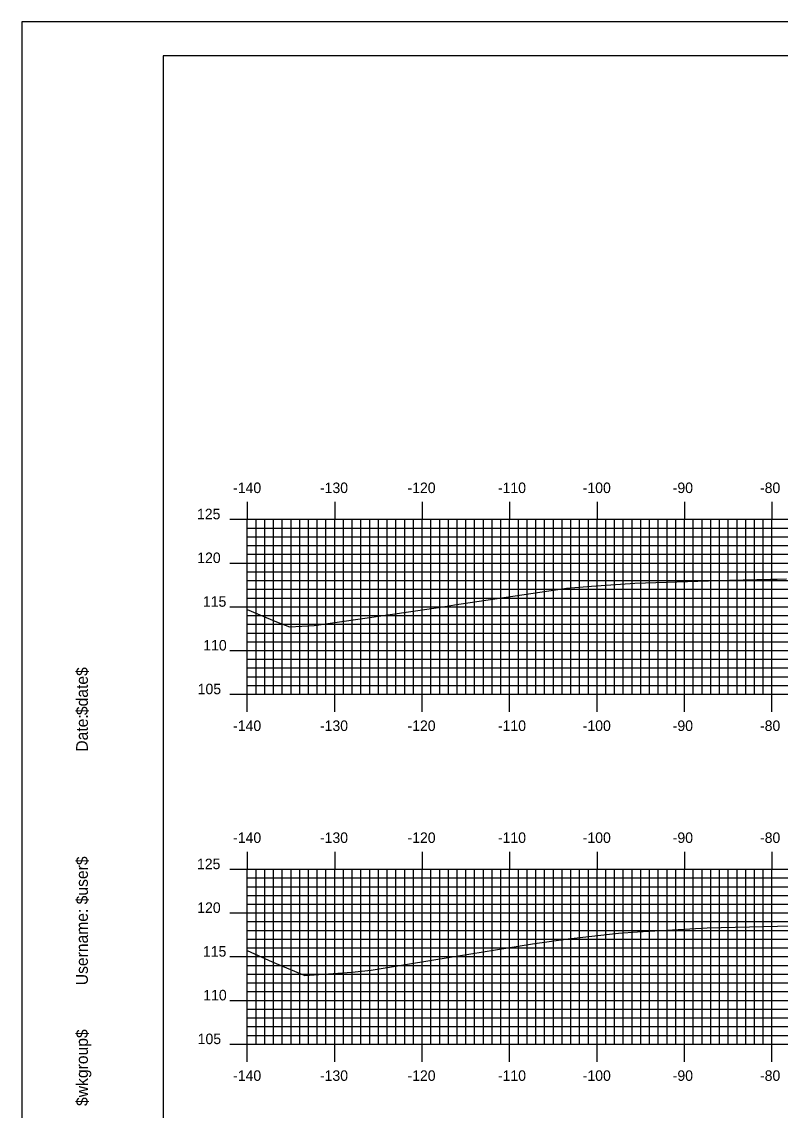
# Model space of a CAD drawing. Extents: x 855074 to 855418, y 366605 to 366825.
# Drawn here: x 855074.3 to 855161, y 366700.5 to 366824.9 of the extents above; entities that cross this region are included whole.
import ezdxf

# ---------------------------------------------------------------- set-up
doc = ezdxf.new("R2010")
doc.units = 0
for name, color, linetype in [('BORDER', 7, 'Continuous'), ('H_V ANNOTATION', 7, 'Continuous'), ('MAJOR', 7, 'Continuous'), ('MINOR', 7, 'Continuous'), ('PLOT BOUNDARY', 7, 'Continuous'), ('S_Roadway_Centerline', 7, 'Continuous')]:
    doc.layers.add(name, color=color, linetype=linetype)

msp = doc.modelspace()

# ---------------------------------------------------------------- linework, layer by layer
at = {"layer": 'BORDER'}
msp.add_lwpolyline([(855090.47, 366611.06), (855410.47, 366611.06), (855410.47, 366821.06), (855090.47, 366821.06)], close=True, dxfattribs=at)
at = {"layer": 'MAJOR'}
for p, q in [((855100.07, 366770.06), (855100.07, 366768.06)), ((855110.07, 366770.06), (855110.07, 366768.06)), ((855120.07, 366770.06), (855120.07, 366768.06)), ((855130.07, 366770.06), (855130.07, 366768.06)), ((855140.07, 366770.06), (855140.07, 366768.06)), ((855150.07, 366770.06), (855150.07, 366768.06)), ((855160.07, 366770.06), (855160.07, 366768.06)), ((855098.07, 366768.06), (855100.07, 366768.06)), ((855100.07, 366768.06), (855380.07, 366768.06)), ((855100.07, 366748.06), (855100.07, 366768.06)), ((855100.07, 366748.06), (855100.07, 366768.06)), ((855100.07, 366768.06), (855380.07, 366768.06)), ((855110.07, 366748.06), (855110.07, 366768.06)), ((855120.07, 366748.06), (855120.07, 366768.06)), ((855130.07, 366748.06), (855130.07, 366768.06)), ((855140.07, 366748.06), (855140.07, 366768.06)), ((855150.07, 366748.06), (855150.07, 366768.06)), ((855160.07, 366748.06), (855160.07, 366768.06)), ((855098.07, 366763.06), (855100.07, 366763.06)), ((855100.07, 366763.06), (855380.07, 366763.06)), ((855098.07, 366758.06), (855100.07, 366758.06)), ((855100.07, 366758.06), (855380.07, 366758.06)), ((855098.07, 366753.06), (855100.07, 366753.06)), ((855100.07, 366753.06), (855380.07, 366753.06)), ((855098.07, 366748.06), (855100.07, 366748.06)), ((855100.07, 366748.06), (855380.07, 366748.06)), ((855100.07, 366748.06), (855380.07, 366748.06)), ((855100.07, 366746.05), (855100.07, 366748.06)), ((855110.07, 366746.05), (855110.07, 366748.06)), ((855120.07, 366746.05), (855120.07, 366748.06)), ((855130.07, 366746.05), (855130.07, 366748.06)), ((855140.07, 366746.05), (855140.07, 366748.06)), ((855150.07, 366746.05), (855150.07, 366748.06)), ((855160.07, 366746.05), (855160.07, 366748.06)), ((855100.07, 366730.06), (855100.07, 366728.06)), ((855110.07, 366730.06), (855110.07, 366728.06)), ((855120.07, 366730.06), (855120.07, 366728.06)), ((855130.07, 366730.06), (855130.07, 366728.06)), ((855140.07, 366730.06), (855140.07, 366728.06)), ((855150.07, 366730.06), (855150.07, 366728.06)), ((855160.07, 366730.06), (855160.07, 366728.06)), ((855098.07, 366728.06), (855100.07, 366728.06)), ((855100.07, 366728.06), (855380.07, 366728.06)), ((855100.07, 366708.06), (855100.07, 366728.06)), ((855100.07, 366708.06), (855100.07, 366728.06)), ((855100.07, 366728.06), (855380.07, 366728.06)), ((855110.07, 366708.06), (855110.07, 366728.06)), ((855120.07, 366708.06), (855120.07, 366728.06)), ((855130.07, 366708.06), (855130.07, 366728.06)), ((855140.07, 366708.06), (855140.07, 366728.06)), ((855150.07, 366708.06), (855150.07, 366728.06)), ((855160.07, 366708.06), (855160.07, 366728.06)), ((855098.07, 366723.06), (855100.07, 366723.06)), ((855100.07, 366723.06), (855380.07, 366723.06)), ((855098.07, 366718.06), (855100.07, 366718.06)), ((855100.07, 366718.06), (855380.07, 366718.06)), ((855098.07, 366713.06), (855100.07, 366713.06)), ((855100.07, 366713.06), (855380.07, 366713.06)), ((855098.07, 366708.06), (855100.07, 366708.06)), ((855100.07, 366708.06), (855380.07, 366708.06)), ((855100.07, 366708.06), (855380.07, 366708.06)), ((855100.07, 366706.05), (855100.07, 366708.06)), ((855110.07, 366706.05), (855110.07, 366708.06)), ((855120.07, 366706.05), (855120.07, 366708.06)), ((855130.07, 366706.05), (855130.07, 366708.06)), ((855140.07, 366706.05), (855140.07, 366708.06)), ((855150.07, 366706.05), (855150.07, 366708.06)), ((855160.07, 366706.05), (855160.07, 366708.06))]:
    msp.add_line(p, q, dxfattribs=at)
at = {"layer": 'MINOR'}
for p, q in [((855101.07, 366748.06), (855101.07, 366768.06)), ((855102.07, 366748.06), (855102.07, 366768.06)), ((855103.07, 366748.06), (855103.07, 366768.06)), ((855104.07, 366748.06), (855104.07, 366768.06)), ((855105.07, 366748.06), (855105.07, 366768.06)), ((855106.07, 366748.06), (855106.07, 366768.06)), ((855107.07, 366748.06), (855107.07, 366768.06)), ((855108.07, 366748.06), (855108.07, 366768.06)), ((855109.07, 366748.06), (855109.07, 366768.06)), ((855111.07, 366748.06), (855111.07, 366768.06)), ((855112.07, 366748.06), (855112.07, 366768.06)), ((855113.07, 366748.06), (855113.07, 366768.06)), ((855114.07, 366748.06), (855114.07, 366768.06)), ((855115.07, 366748.06), (855115.07, 366768.06)), ((855116.07, 366748.06), (855116.07, 366768.06)), ((855117.07, 366748.06), (855117.07, 366768.06)), ((855118.07, 366748.06), (855118.07, 366768.06)), ((855119.07, 366748.06), (855119.07, 366768.06)), ((855121.07, 366748.06), (855121.07, 366768.06)), ((855122.07, 366748.06), (855122.07, 366768.06)), ((855123.07, 366748.06), (855123.07, 366768.06)), ((855124.07, 366748.06), (855124.07, 366768.06)), ((855125.07, 366748.06), (855125.07, 366768.06)), ((855126.07, 366748.06), (855126.07, 366768.06)), ((855127.07, 366748.06), (855127.07, 366768.06)), ((855128.07, 366748.06), (855128.07, 366768.06)), ((855129.07, 366748.06), (855129.07, 366768.06)), ((855131.07, 366748.06), (855131.07, 366768.06)), ((855132.07, 366748.06), (855132.07, 366768.06)), ((855133.07, 366748.06), (855133.07, 366768.06)), ((855134.07, 366748.06), (855134.07, 366768.06)), ((855135.07, 366748.06), (855135.07, 366768.06)), ((855136.07, 366748.06), (855136.07, 366768.06)), ((855137.07, 366748.06), (855137.07, 366768.06)), ((855138.07, 366748.06), (855138.07, 366768.06)), ((855139.07, 366748.06), (855139.07, 366768.06)), ((855141.07, 366748.06), (855141.07, 366768.06)), ((855142.07, 366748.06), (855142.07, 366768.06)), ((855143.07, 366748.06), (855143.07, 366768.06)), ((855144.07, 366748.06), (855144.07, 366768.06)), ((855145.07, 366748.06), (855145.07, 366768.06)), ((855146.07, 366748.06), (855146.07, 366768.06)), ((855147.07, 366748.06), (855147.07, 366768.06)), ((855148.07, 366748.06), (855148.07, 366768.06)), ((855149.07, 366748.06), (855149.07, 366768.06)), ((855151.07, 366748.06), (855151.07, 366768.06)), ((855152.07, 366748.06), (855152.07, 366768.06)), ((855153.07, 366748.06), (855153.07, 366768.06)), ((855154.07, 366748.06), (855154.07, 366768.06)), ((855155.07, 366748.06), (855155.07, 366768.06)), ((855156.07, 366748.06), (855156.07, 366768.06)), ((855157.07, 366748.06), (855157.07, 366768.06)), ((855158.07, 366748.06), (855158.07, 366768.06)), ((855159.07, 366748.06), (855159.07, 366768.06)), ((855100.07, 366767.06), (855380.07, 366767.06)), ((855100.07, 366767.06), (855102.07, 366767.06)), ((855100.07, 366766.06), (855380.07, 366766.06)), ((855100.07, 366766.06), (855102.07, 366766.06)), ((855100.07, 366765.06), (855380.07, 366765.06)), ((855100.07, 366765.06), (855102.07, 366765.06)), ((855100.07, 366764.06), (855380.07, 366764.06)), ((855100.07, 366764.06), (855102.07, 366764.06)), ((855100.07, 366762.06), (855380.07, 366762.06)), ((855100.07, 366762.06), (855102.07, 366762.06)), ((855100.07, 366761.06), (855380.07, 366761.06)), ((855100.07, 366761.06), (855102.07, 366761.06)), ((855100.07, 366760.06), (855380.07, 366760.06)), ((855100.07, 366760.06), (855102.07, 366760.06)), ((855100.07, 366759.06), (855380.07, 366759.06)), ((855100.07, 366759.06), (855102.07, 366759.06)), ((855100.07, 366757.06), (855380.07, 366757.06)), ((855100.07, 366757.06), (855102.07, 366757.06)), ((855100.07, 366756.06), (855380.07, 366756.06)), ((855100.07, 366756.06), (855102.07, 366756.06)), ((855100.07, 366755.06), (855380.07, 366755.06)), ((855100.07, 366755.06), (855102.07, 366755.06)), ((855100.07, 366754.06), (855380.07, 366754.06)), ((855100.07, 366754.06), (855102.07, 366754.06)), ((855100.07, 366752.06), (855380.07, 366752.06)), ((855100.07, 366752.06), (855102.07, 366752.06)), ((855100.07, 366751.06), (855380.07, 366751.06)), ((855100.07, 366751.06), (855102.07, 366751.06)), ((855100.07, 366750.06), (855380.07, 366750.06)), ((855100.07, 366750.06), (855102.07, 366750.06)), ((855100.07, 366749.06), (855380.07, 366749.06)), ((855100.07, 366749.06), (855102.07, 366749.06)), ((855101.07, 366708.06), (855101.07, 366728.06)), ((855102.07, 366708.06), (855102.07, 366728.06)), ((855103.07, 366708.06), (855103.07, 366728.06)), ((855104.07, 366708.06), (855104.07, 366728.06)), ((855105.07, 366708.06), (855105.07, 366728.06)), ((855106.07, 366708.06), (855106.07, 366728.06)), ((855107.07, 366708.06), (855107.07, 366728.06)), ((855108.07, 366708.06), (855108.07, 366728.06)), ((855109.07, 366708.06), (855109.07, 366728.06)), ((855111.07, 366708.06), (855111.07, 366728.06)), ((855112.07, 366708.06), (855112.07, 366728.06)), ((855113.07, 366708.06), (855113.07, 366728.06)), ((855114.07, 366708.06), (855114.07, 366728.06)), ((855115.07, 366708.06), (855115.07, 366728.06)), ((855116.07, 366708.06), (855116.07, 366728.06)), ((855117.07, 366708.06), (855117.07, 366728.06)), ((855118.07, 366708.06), (855118.07, 366728.06)), ((855119.07, 366708.06), (855119.07, 366728.06)), ((855121.07, 366708.06), (855121.07, 366728.06)), ((855122.07, 366708.06), (855122.07, 366728.06)), ((855123.07, 366708.06), (855123.07, 366728.06)), ((855124.07, 366708.06), (855124.07, 366728.06)), ((855125.07, 366708.06), (855125.07, 366728.06)), ((855126.07, 366708.06), (855126.07, 366728.06)), ((855127.07, 366708.06), (855127.07, 366728.06)), ((855128.07, 366708.06), (855128.07, 366728.06)), ((855129.07, 366708.06), (855129.07, 366728.06)), ((855131.07, 366708.06), (855131.07, 366728.06)), ((855132.07, 366708.06), (855132.07, 366728.06)), ((855133.07, 366708.06), (855133.07, 366728.06)), ((855134.07, 366708.06), (855134.07, 366728.06)), ((855135.07, 366708.06), (855135.07, 366728.06)), ((855136.07, 366708.06), (855136.07, 366728.06)), ((855137.07, 366708.06), (855137.07, 366728.06)), ((855138.07, 366708.06), (855138.07, 366728.06)), ((855139.07, 366708.06), (855139.07, 366728.06)), ((855141.07, 366708.06), (855141.07, 366728.06)), ((855142.07, 366708.06), (855142.07, 366728.06)), ((855143.07, 366708.06), (855143.07, 366728.06)), ((855144.07, 366708.06), (855144.07, 366728.06)), ((855145.07, 366708.06), (855145.07, 366728.06)), ((855146.07, 366708.06), (855146.07, 366728.06)), ((855147.07, 366708.06), (855147.07, 366728.06)), ((855148.07, 366708.06), (855148.07, 366728.06)), ((855149.07, 366708.06), (855149.07, 366728.06)), ((855151.07, 366708.06), (855151.07, 366728.06)), ((855152.07, 366708.06), (855152.07, 366728.06)), ((855153.07, 366708.06), (855153.07, 366728.06)), ((855154.07, 366708.06), (855154.07, 366728.06)), ((855155.07, 366708.06), (855155.07, 366728.06)), ((855156.07, 366708.06), (855156.07, 366728.06)), ((855157.07, 366708.06), (855157.07, 366728.06)), ((855158.07, 366708.06), (855158.07, 366728.06)), ((855159.07, 366708.06), (855159.07, 366728.06)), ((855100.07, 366727.06), (855380.07, 366727.06)), ((855100.07, 366727.06), (855102.07, 366727.06)), ((855100.07, 366726.06), (855380.07, 366726.06)), ((855100.07, 366726.06), (855102.07, 366726.06)), ((855100.07, 366725.06), (855380.07, 366725.06)), ((855100.07, 366725.06), (855102.07, 366725.06)), ((855100.07, 366724.06), (855380.07, 366724.06)), ((855100.07, 366724.06), (855102.07, 366724.06)), ((855100.07, 366722.06), (855380.07, 366722.06)), ((855100.07, 366722.06), (855102.07, 366722.06)), ((855100.07, 366721.06), (855380.07, 366721.06)), ((855100.07, 366721.06), (855102.07, 366721.06)), ((855100.07, 366720.06), (855380.07, 366720.06)), ((855100.07, 366720.06), (855102.07, 366720.06)), ((855100.07, 366719.06), (855380.07, 366719.06)), ((855100.07, 366719.06), (855102.07, 366719.06)), ((855100.07, 366717.06), (855380.07, 366717.06)), ((855100.07, 366717.06), (855102.07, 366717.06)), ((855100.07, 366716.06), (855380.07, 366716.06)), ((855100.07, 366716.06), (855102.07, 366716.06)), ((855100.07, 366715.06), (855380.07, 366715.06)), ((855100.07, 366715.06), (855102.07, 366715.06)), ((855100.07, 366714.06), (855380.07, 366714.06)), ((855100.07, 366714.06), (855102.07, 366714.06)), ((855100.07, 366712.06), (855380.07, 366712.06)), ((855100.07, 366712.06), (855102.07, 366712.06)), ((855100.07, 366711.06), (855380.07, 366711.06)), ((855100.07, 366711.06), (855102.07, 366711.06)), ((855100.07, 366710.06), (855380.07, 366710.06)), ((855100.07, 366710.06), (855102.07, 366710.06)), ((855100.07, 366709.06), (855380.07, 366709.06)), ((855100.07, 366709.06), (855102.07, 366709.06))]:
    msp.add_line(p, q, dxfattribs=at)
at = {"layer": 'PLOT BOUNDARY'}
msp.add_lwpolyline([(855074.28, 366604.94), (855414.28, 366604.94), (855414.28, 366824.94), (855074.28, 366824.94)], close=True, dxfattribs=at)
at = {"layer": 'S_Roadway_Centerline'}
for points in [[(855100.07, 366757.76), (855103.43, 366756.32), (855104.91, 366755.76), (855107.7, 366755.93), (855121.67, 366757.95), (855122.93, 366758.14), (855123.76, 366758.29), (855135.59, 366760.05), (855136.58, 366760.19), (855139.43, 366760.42), (855144.38, 366760.74), (855155.21, 366761.09), (855159.9, 366761.21), (855160.68, 366761.23), (855161.73, 366761.27)], [(855100.07, 366718.76), (855102.92, 366717.48), (855106.66, 366715.91), (855112.04, 366716.29), (855114.22, 366716.53), (855121.4, 366717.71), (855132.69, 366719.53), (855136.78, 366720.11), (855142.52, 366720.75), (855144.71, 366720.89), (855152.67, 366721.34), (855160.69, 366721.56), (855163.83, 366721.62)]]:
    msp.add_lwpolyline(points, dxfattribs=at)

# ---------------------------------------------------------------- texts
at = {"layer": 'BORDER'}
for s, p in [('$date$', (855081.84, 366745.67)), ('Date:', (855081.84, 366741.49)), ('$user$', (855081.84, 366724.04)), ('Username:', (855081.84, 366714.79)), ('$wkgroup$', (855081.84, 366700.99))]:
    msp.add_text(s, height=1.339, rotation=90, dxfattribs=at).set_placement(p)
at = {"layer": 'H_V ANNOTATION'}
for s, p in [('-140', (855098.45, 366771.06)), ('-130', (855108.38, 366771.06)), ('-120', (855118.39, 366771.06)), ('-110', (855128.73, 366771.06)), ('-100', (855138.43, 366771.06)), ('-90', (855148.72, 366771.06)), ('-80', (855158.7, 366771.06)), ('125', (855094.32, 366768.06)), ('120', (855094.35, 366763.06)), ('115', (855095, 366758.06)), ('110', (855095.04, 366753.06)), ('105', (855094.4, 366748.06)), ('-140', (855098.45, 366743.86)), ('-130', (855108.38, 366743.86)), ('-120', (855118.39, 366743.86)), ('-110', (855128.73, 366743.86)), ('-100', (855138.43, 366743.86)), ('-90', (855148.72, 366743.86)), ('-80', (855158.7, 366743.86)), ('-140', (855098.45, 366731.06)), ('-130', (855108.38, 366731.06)), ('-120', (855118.39, 366731.06)), ('-110', (855128.73, 366731.06)), ('-100', (855138.43, 366731.06)), ('-90', (855148.72, 366731.06)), ('-80', (855158.7, 366731.06)), ('125', (855094.32, 366728.06)), ('120', (855094.35, 366723.06)), ('115', (855095, 366718.06)), ('110', (855095.04, 366713.06)), ('105', (855094.4, 366708.06)), ('-140', (855098.45, 366703.86)), ('-130', (855108.38, 366703.86)), ('-120', (855118.39, 366703.86)), ('-110', (855128.73, 366703.86)), ('-100', (855138.43, 366703.86)), ('-90', (855148.72, 366703.86)), ('-80', (855158.7, 366703.86))]:
    msp.add_text(s, height=1.2, dxfattribs=at).set_placement(p)
at = {"layer": 'MAJOR'}
for p in [(855100.06, 366748.06), (855100.06, 366708.06)]:
    msp.add_text('-', height=0.012, dxfattribs=at).set_placement(p)

doc.saveas('drawing.dxf')
